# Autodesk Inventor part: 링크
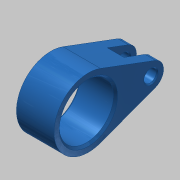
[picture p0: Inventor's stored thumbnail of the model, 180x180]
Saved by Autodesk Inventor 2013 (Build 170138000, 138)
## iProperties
Created: 2016-08
Part Number: 링크
Material: 강철, 탄소
Document SubType Name: Modeling
Designer: mduedu
Density: 7.87 g/cm^3
Mass: 80.4025 g
Surface Area: 54.1946 cm^2
Volume: 10.2163 cm^3
Author: mduedu
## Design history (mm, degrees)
sketch "스케치1"
  geometry: L1 (32.1, 5.62)-(5.775, 15.456); L2 (32.1, -5.62)-(5.775, -15.456); C1 r 13 at (0, 0); C2 r 3 at (30, 0); A1 r 16.5 centre (0, 0) between (5.775, 15.456) and (5.775, -15.456); A2 r 6 centre (30, 0) between (32.1, 5.62) and (32.1, -5.62); 1 further point
  constraints: 4 centre point, 4 end point, 4 point on circle, 4 tangent, 3 coincident, 1 horizontal alignment
  dimensions: "d0" = 33 diameter of A1; "d2" = 12 diameter of A2; "d3" = 30 distance of A2.centre point (0, 0); "d4" = 26 diameter of C1; "d5" = 6 diameter of C2
extrude "돌출1" new body sketch "스케치1" stored distance "d6" = 18; taper "d7" = 0 deg
sketch "스케치2"
  geometry: L1 (-9, 36)-(9, 36) reference; L2 (0, 0)-(0, 36); L3 (-4, 36)-(4, 36); L4 (4, 36)-(4, 22); L5 (4, 22)-(-4, 22); L6 (-4, 22)-(-4, 36)
  constraints: 10 end point, 2 midpoint, 2 parallel, 1 horizontal, 1 perpendicular, 1 point on line
  dimensions: "d8" = 8 distance between parallel lines of L4 L6; "d10" = 14 distance of L3.end L4.end
extrude "돌출2" cut sketch "스케치2" stored distance "d11" = 20; taper "d12" = 0 deg
chamfer "모따기1" distance "d13" = 1; stored, may be unused: second distance "d14" = 2, angle "d15" = 45 deg
chamfer "모따기2" distance "d16" = 0.5; stored, may be unused: second distance "d17" = 2, angle "d18" = 45 deg
node "솔리드1"
